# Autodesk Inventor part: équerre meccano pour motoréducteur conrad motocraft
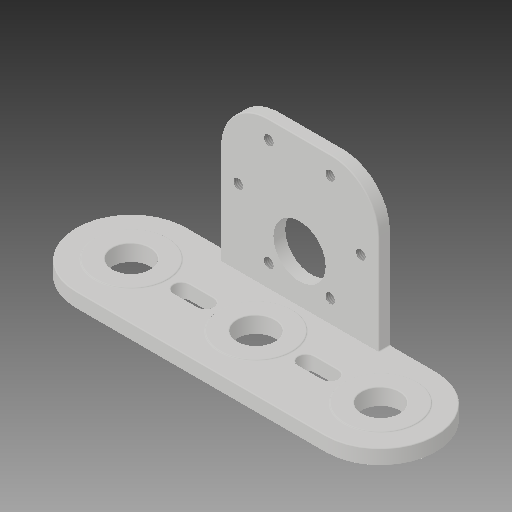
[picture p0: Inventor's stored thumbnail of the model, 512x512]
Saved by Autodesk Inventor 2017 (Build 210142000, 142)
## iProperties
Part Number: équerre meccano pour motoréducteur conrad motocraft
Material: Générique
Document SubType Name: Modeling
Designer: ficho
Density: 1 g/cm^3
Appearance: Par défaut
Mass: 11.9885 g
Surface Area: 84.7912 cm^2
Volume: 11.9885 cm^3
Author: ficho
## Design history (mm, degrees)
sketch "Esquisse2"
  geometry: L1 (-20, 20)-(20, 20); L2 (20, 20)-(20, -20); L3 (20, -20)-(-20, -20); L4 (-20, -20)-(-20, 20); 1 further point
  constraints: 8 end point, 2 parallel, 1 horizontal, 1 perpendicular
  dimensions: "d0" = 20 distance from line of point (0, 0) L4; "d1" = 40 distance between parallel lines of L2 L4 (= 2 x d0); "d2" = 20 distance from line of point (0, 0) L1 (= d0); "d3" = 40 distance between parallel lines of L3 L1 (= d1)
extrude "Extrusion1" new body sketch "Esquisse2" distance "d4" = 3; taper "d5" = 0 deg
sketch "Esquisse3"
  geometry: L1 (20, 20)-(-20, 20) reference; L2 (-20, 20)-(-20, -20) reference; L3 (-20, -20)-(20, -20) reference; L4 (20, -20)-(20, 20) reference; L5 (20, -20)-(20, 20) reference; L6 (-20, -20)-(20, -20); L7 (20, -20)-(20, -17); L8 (20, -17)-(-20, -17); L9 (-20, -17)-(-20, -20); 1 further point
  constraints: 8 end point, 2 parallel, 1 horizontal, 1 perpendicular, 1 point on line
  dimensions: "d6" = 3 distance of L7.end L6.end
extrude "Extrusion2" join sketch "Esquisse3" distance "d7" = 17; taper "d8" = 0 deg
sketch "Esquisse4"
  geometry: L1 (-20, -20)-(20, -20) reference; C1 r 6.6 at (0, -5); 1 further point
  constraints: 1 centre point
  dimensions: "d9" = 13.2 diameter of C1; "d10" = 15 distance from line of L1 C1.centre
extrude "Extrusion3" cut sketch "Esquisse4" stored distance "d11" = 17; taper "d12" = 0 deg
sketch "Esquisse5" dims "d15" = 31
  geometry: C1 r 6.6 at (0, -5) reference; 8 further points
  constraints: 1 horizontal alignment, 9 other
  dimensions: "d14" = 7 distance of point (0, 2) C1.centre; "d18" = 360 deg dimension on point (0, 2) point (-15.5, 2) (derived)
hole "Perçage1" sketch "Esquisse5" at (-15.5, 2), (-7.75, 15.423), (7.75, 15.423), (15.5, 2), (7.75, -11.423), (-7.75, -11.423) diameter "d20" = 2.459; stored, may be unused: countersink angle "d24" = 82 deg, drill point angle "d26" = 118 deg; dims "d21" = 6, "d22" = 3.023, "d23" = 2, "d25" = 8.8
sketch "Esquisse6"
  geometry: L1 (-20, -20)-(20, -20) reference; L2 (20, -20)-(20, -17) reference; L3 (20, -17)-(-20, -17) reference; L4 (-20, -17)-(-20, -20) reference; 1 further point
extrude "Extrusion4" cut sketch "Esquisse6" stored distance "d27" = 10; taper "d28" = 0 deg
sketch "Esquisse7"
  geometry: L1 (40, -3)-(0, -3) reference; L2 (-11.5, 25)-(51.5, 25); L3 (51.5, -3)-(-11.5, -3); C1 r 4.75 at (20, 11); C2 r 4.75 at (51.5, 11); C3 r 4.75 at (-11.5, 11); A1 r 14 centre (51.5, 11) between (51.5, -3) and (51.5, 25); A2 r 14 centre (-11.5, 11) between (-11.5, 25) and (-11.5, -3); 1 further point
  constraints: 5 centre point, 4 end point, 4 point on circle, 3 tangent, 2 coincident, 1 point on line
  dimensions: "d29" = 9.5 diameter of C1 (= d30); "d30" = 9.5 diameter of C2; "d31" = 9.5 diameter of C3 (= d29); "d32" = 14 distance from line of L1 C2.centre; "d33" = 14 distance from line of L1 C1.centre (= d32); "d34" = 14 distance from line of C3.centre L1 (= d32); "d35" = 31.5 distance of C2.centre C1.centre; "d36" = 31.5 distance of C3.centre C1.centre (= d35)
extrude "Extrusion5" join sketch "Esquisse7" distance "d37" = 3.8; taper "d38" = 0 deg
fillet "Congé1" dims "d39" = 0.25
fillet "Congé2" dims "d40" = 12
sketch "Esquisse8"
  geometry: L1 (38.75, -9)-(32.75, -9); L2 (32.75, -13)-(38.75, -13); L3 (-11.5, -25)-(51.5, -25) reference; L4 (51.5, -24.75)-(-11.5, -24.75) reference; C1 r 4.75 at (51.5, -11) reference; C2 r 4.75 at (20, -11) reference; A1 r 2 centre (32.75, -11) between (32.75, -9) and (32.75, -13); A2 r 2 centre (38.75, -11) between (38.75, -13) and (38.75, -9); 1 further point
  constraints: 4 end point, 4 point on circle, 4 tangent, 2 centre point, 1 parallel
  dimensions: "d41" = 4 diameter of A1; "d42" = 4 diameter of A2 (= d41); "d43" = 6 distance of A2.centre A1.centre; "d47" = 12 distance between parallel lines of L3 L2; "d48" = 12.75 distance of A2.centre C1.centre
extrude "Extrusion6" cut sketch "Esquisse8" stored distance "d57" = 3.8; taper "d58" = 0 deg
fillet "Congé3" dims "d59" = 0.25
pattern_linear "Réseau rectangulaire1" dims "d62" = 31.5
sketch "Esquisse9"
  geometry: L1 (32.75, -13.25)-(38.75, -13.25) reference; L2 (38.75, -8.75)-(32.75, -8.75) reference; L3 (-0.25, 2.75)-(-0.25, 0.25) reference; L4 (-11.5, 2.75)-(-0.25, 2.75) reference; L5 (51.5, -24.75)-(-11.5, -24.75) reference; L6 (40.25, 2.75)-(51.5, 2.75) reference; L7 (40.25, 0.25)-(40.25, 2.75) reference; L8 (0.183, 0)-(39.817, 0) reference; L9 (1.25, -13.25)-(7.25, -13.25) reference; L10 (7.25, -8.75)-(1.25, -8.75) reference; C1 r 4.75 at (51.5, -11) reference; C2 r 4.75 at (-11.5, -11) reference; C3 r 4.75 at (51.5, -11) reference; C4 r 4.75 at (20, -11) reference; C5 r 4.75 at (20, -11) reference; C6 r 9.15 at (51.5, -11); C7 r 9.15 at (20, -11); C8 r 9.15 at (-11.5, -11); A1 r 2.25 centre (38.75, -11) between (38.75, -13.25) and (38.75, -8.75) reference; A2 r 2.25 centre (32.75, -11) between (32.75, -8.75) and (32.75, -13.25) reference; A3 r 13.75 centre (-11.5, -11) between (-11.5, 2.75) and (-11.5, -24.75) reference; A4 r 13.75 centre (51.5, -11) between (51.5, -24.75) and (51.5, 2.75) reference; A5 r 2.25 centre (7.25, -11) between (7.25, -13.25) and (7.25, -8.75) reference; A6 r 2.25 centre (1.25, -11) between (1.25, -8.75) and (1.25, -13.25) reference; 1 further point
  constraints: 3 centre point, 3 coincident, 2 other
  dimensions: "d63" = 18.3 diameter of C6; "d64" = 18.3 diameter of C7; "d65" = 18.3 diameter of C8
extrude "Extrusion7" join sketch "Esquisse9" distance "d66" = 0.25; taper "d67" = 0 deg
fillet "Congé4" dims "d68" = 0.25
fillet "Congé5" dims "d69" = 0.25
node "Plan de construction1"
mirror "Symétrie1"
node "Solide1"
node "Boucle projetée1"
node "Boucle projetée2"
node "Boucle projetée3"
other parameters: "d70" = -1.9
